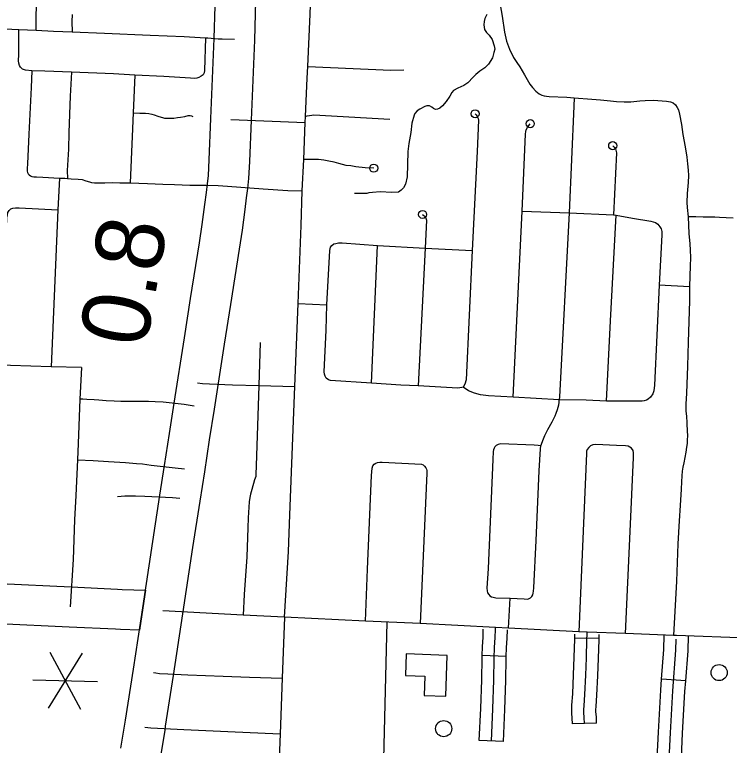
# Model space of a CAD drawing. Extents: x 653372 to 905732, y 627442 to 787275.
# Drawn here: x 688877 to 693311, y 773364 to 777895 of the extents above; entities that cross this region are included whole.
import ezdxf

# ---------------------------------------------------------------- set-up
doc = ezdxf.new("R2010")
doc.units = 0
for name, color, linetype in [('10', 7, 'Continuous'), ('32', 7, 'Continuous'), ('33', 7, 'Continuous'), ('34', 7, 'Continuous'), ('35', 7, 'Continuous'), ('48', 7, 'Continuous'), ('56', 7, 'Continuous'), ('58', 7, 'Continuous'), ('6', 7, 'Continuous')]:
    doc.layers.add(name, color=color, linetype=linetype)

msp = doc.modelspace()

# ---------------------------------------------------------------- linework, layer by layer
at = {"layer": '10'}
for points in [[(689536.7, 773346.1), (689560.5, 773495.3), (689564.1, 773520.3), (689614.1, 773835.2), (689671.8, 774217.4), (689733.5, 774627.8), (689778.5, 774916.3), (689807.4, 775098.7), (689837.2, 775296.7), (689866.9, 775486.7), (689929.8, 775890.1), (689968.3, 776135.9), (690023.1, 776479.5), (690040.6, 776594.7), (690056.9, 776718.6), (690066.3, 776792.3), (690074.1, 776846.8), (690079.2, 776898.2), (690083.7, 776995.5), (690093.7, 777250.6), (690115, 777746.6), (690126.4, 778153.9)], [(690376.3, 778145.3), (690364.8, 777737.8), (690343.5, 777240.3), (690333.5, 776984.8), (690328.7, 776880.1), (690322.4, 776816.7), (690314.1, 776758.7), (690304.8, 776686.4), (690288.1, 776559.7), (690270.2, 776441.1), (690215.2, 776096.9), (690176.9, 775851.5), (690113.9, 775448.2), (690084.3, 775258.8), (690054.4, 775060.6), (690025.5, 774877.5), (689980.6, 774590), (689919, 774180.1), (689861.2, 773796.9), (689811.3, 773483.1), (689807.8, 773458.1), (689783.7, 773307.2)], [(687265.9, 774433.2), (687410.6, 774429.4), (687546.1, 774423.7), (687592, 774420.9), (687915.2, 774404.3), (688264.9, 774389.4), (688488.7, 774378.5), (688787.8, 774366.5), (689227.2, 774347), (689516, 774333.1), (689544.5, 774331.3), (689688.3, 774327), (689650.8, 774078)], [(689650.8, 774078), (689533.1, 774081.6), (689502.4, 774083.5), (689215.7, 774097.2), (688777.2, 774116.7), (688477.6, 774128.8), (688253.6, 774139.6), (687903.4, 774154.6), (687578.1, 774171.3), (687533.4, 774174), (687402, 774179.6), (687259.3, 774183.3)]]:
    msp.add_lwpolyline(points, dxfattribs=at)
at = {"layer": '32'}
for p, q in [((692502.6, 774025.7), (692352.6, 774028.1)), ((691927.3, 773914.9), (691777.5, 773920.8)), ((693040.1, 773763), (692890.5, 773774.7)), ((692486.8, 773501), (692336.9, 773498)), ((691909.5, 773386.8), (691759.7, 773393.6))]:
    msp.add_line(p, q, dxfattribs=at)
for points in [[(691777.5, 773920.8), (691779.6, 773974.8), (691782.9, 774035.4), (691784.7, 774085)], [(691834.6, 773390.2), (691843.6, 773589.7), (691849.6, 773767.8), (691851.9, 773904.5), (691854.5, 773971.2), (691857.8, 774031.9), (691859.7, 774082.2)], [(691927.3, 773914.9), (691929.4, 773967.7), (691932.8, 774028.5), (691934.6, 774079.5)], [(692352.6, 774028.1), (692353, 774052.7)], [(692336.9, 773498), (692336.2, 773532.3), (692333.4, 773564.2), (692333.3, 773588.2), (692334.7, 773613.2), (692339.3, 773682.5), (692344.7, 773802.1), (692349.1, 773910.1), (692352.5, 774022.4), (692352.6, 774028.1)], [(692411.8, 773499.5), (692411.1, 773536.3), (692408.4, 773567.6), (692408.3, 773586.2), (692409.6, 773608.6), (692414.2, 773678.4), (692419.6, 773798.9), (692424.1, 773907.4), (692427.5, 774020.7), (692428, 774051.5)], [(692486.8, 773501), (692486, 773540.3), (692483.4, 773571), (692483.3, 773584.2), (692484.5, 773604), (692489, 773674.2), (692494.5, 773795.7), (692499, 773904.7), (692502.5, 774018.9), (692502.6, 774025.7)], [(692502.6, 774025.7), (692503, 774050.3)], [(692890.5, 773774.7), (692904.9, 773958), (692907.6, 774047.5)], [(692930.4, 772714), (692924.4, 772800), (692927.7, 772910.2), (692932.1, 773057.1), (692936.2, 773235.9), (692946.1, 773442.3), (692960, 773701.7), (692979.9, 773953.9), (692981.9, 774021.6)], [(693040.1, 773763), (693054.8, 773949.8), (693057.6, 774042.7)], [(691759.7, 773393.6), (691768.7, 773592.6), (691774.6, 773769.7), (691776.9, 773906.6), (691777.5, 773920.8)], [(691909.5, 773386.8), (691918.6, 773586.7), (691924.6, 773765.9), (691926.9, 773902.4), (691927.3, 773914.9)], [(692861.6, 773245.2), (692871.2, 773446.1), (692885.2, 773706.6), (692890.5, 773774.7)], [(693011.4, 773238.1), (693021, 773438.5), (693034.9, 773696.7), (693040.1, 773763)]]:
    msp.add_lwpolyline(points, dxfattribs=at)
at = {"layer": '33'}
for points in [[(690550.6, 774158.3), (690575.6, 774566.7), (690583.4, 774794.3), (690615.6, 775588.4), (690635.5, 776104.2), (690654, 776588.6), (690661.4, 776802.5), (690670.9, 776996.8), (690678.7, 777225.6), (690681.8, 777264.6), (690690.8, 777501.7), (690696.6, 777572.9), (690711, 777897.6), (690715.4, 778011.1), (690718.5, 778085.4), (690718.1, 778132), (690718.9, 778221.3), (690716.2, 778348), (690715.4, 778462.1)], [(689010.4, 777798.4), (689010.7, 777894.8), (689016.4, 778027.3)], [(689233.4, 777895.5), (689232.7, 777853.6), (689233.8, 777788.2)], [(688052.5, 777836.9), (688146.7, 777834.1), (688304, 777826.6), (688436.3, 777820.5), (688587.6, 777816.7), (688643.2, 777815), (688903.1, 777803.7), (689010.4, 777798.4), (689117.4, 777792.4), (689233.8, 777788.2), (689434, 777779.4), (689717.1, 777767.5), (689929.1, 777759), (690061.3, 777752.3), (690076.5, 777751.8), (690138.8, 777745.8), (690163.5, 777744.3), (690239.9, 777742.2)], [(690061.3, 777752.3), (690055.1, 777548.3), (690052, 777535.2), (690046.7, 777522.9), (690033.3, 777513.6), (690019.8, 777505), (690007.2, 777500.5), (689994.7, 777499.5), (689967, 777501.7), (689801.5, 777511.5), (689622.7, 777520.1), (689489.6, 777528.5), (689230.7, 777537.6), (689063.5, 777545.5), (688983.4, 777546.5), (688944, 777551.1), (688925.4, 777558), (688913.3, 777568.7), (688906.7, 777580), (688902.2, 777594.7), (688901.3, 777608.6), (688902.5, 777648.2), (688903.1, 777803.7)], [(688983.4, 777546.5), (688979.1, 777444.5), (688965.2, 777155), (688957.3, 776970.6), (688955.5, 776942.1), (688955.4, 776925), (688957.5, 776915.4), (688961.1, 776908.8), (688967.6, 776901.5), (688974.5, 776895.1), (688983, 776892.5), (688996.7, 776889.7), (689013.4, 776889.2), (689051.4, 776887.6), (689154.4, 776881.6), (689187.7, 776881.1), (689203.9, 776880.1), (689227.6, 776878), (689271, 776874.8), (689295.7, 776872.1), (689319.6, 776864.8), (689340.8, 776858.4), (689354, 776854.7), (689372.5, 776852.7), (689401.2, 776852.3), (689436.4, 776852.2), (689483.9, 776854.1), (689529.7, 776853.2), (689594.1, 776851.8), (689701.5, 776847.6), (689796.1, 776844.7), (689869.3, 776841.6), (689963.2, 776838.8), (690064.4, 776837.2), (690140.5, 776835.4), (690198.3, 776831.8)], [(690696.6, 777572.9), (691211.4, 777550.1), (691292.2, 777553.3)], [(689230.7, 777537.6), (689221.7, 777390.3), (689213.8, 777165.1), (689211.2, 777060.8), (689203.2, 776929.7), (689203.9, 776880.1)], [(689622.7, 777520.1), (689611.4, 777285.6), (689605.4, 777140.5), (689594.1, 776851.8)], [(692346.7, 777328.2), (692316.2, 776666.5), (692257.5, 775524.6), (692255, 775507.3)], [(690681.8, 777264.6), (690691.9, 777266.9), (690707.2, 777269.7), (690721.7, 777272.4), (690733, 777273.7), (691205.5, 777247.5)], [(691733.9, 777280.5), (691740, 777274.1), (691747.4, 777263), (691753.3, 777251.1), (691755.3, 777240.1), (691745.6, 777046.2), (691716.2, 776432.4), (691677.4, 775631.1), (691670.3, 775604), (691659.3, 775584.6), (691651, 775582.7), (691627.5, 775579.6), (691379.9, 775594), (691273.8, 775597.9), (691089.9, 775609.7), (690837.2, 775626.6), (690823.9, 775631), (690810.2, 775641.5), (690802.8, 775654.2), (690799.3, 775665.2), (690796.7, 775680.1), (690810.6, 775937.9), (690814.6, 776094.7), (690833.3, 776433.5), (690837, 776453.6), (690845.1, 776463.5), (690857.1, 776473.3), (690868.9, 776476.9), (690885.4, 776480.3), (690909.6, 776479.5), (691129, 776464.4), (691423.2, 776446.8), (691716.2, 776432.4)], [(690218.6, 777245.4), (690678.7, 777225.6)], [(691969.4, 775523.8), (691993.2, 775995.5), (692026.1, 776676.8), (692046.7, 777155.1), (692048.8, 777171.4), (692050.7, 777181.5), (692058.1, 777194.6), (692067.8, 777208.3), (692076, 777219)], [(692587.3, 777082.6), (692595.6, 777073.8), (692604.6, 777062.6), (692607.5, 777053.9), (692610.9, 777038.2), (692591.6, 776653)], [(691104.9, 776943.2), (691052, 776945.6), (690993.7, 776952.2), (690961.7, 776957.2), (690934.6, 776960.4), (690887.6, 776973), (690859, 776980.3), (690826.3, 776986.9), (690795.1, 776991.9), (690761.6, 776996.9), (690722.3, 776996.5), (690670.9, 776996.8)], [(689154.4, 776881.6), (689145.4, 776685.4), (689102.5, 775712.1)], [(690198.3, 776831.8), (690279.9, 776825.2), (690418.7, 776815.1), (690571.1, 776805.4), (690661.4, 776802.5)], [(689291, 775706.1), (689102.5, 775712.1), (688851.9, 775718.9), (688829.3, 775722.3), (688815.3, 775728.1), (688802.8, 775740.7), (688793.1, 775755.8), (688790.9, 775770.8), (688792.6, 775807.9), (688800.7, 776007.1), (688819.3, 776402.1), (688829, 776634.7), (688831.8, 776651.9), (688835.6, 776668.9), (688842.7, 776680.9), (688853.6, 776690.1), (688866.6, 776694.4), (688881.9, 776697), (688904.5, 776697.4), (689145.4, 776685.4)], [(691407.7, 776656.3), (691415.3, 776649.8), (691423.6, 776641), (691427.3, 776633.9), (691431.6, 776621.3), (691423.2, 776446.8)], [(692026.1, 776676.8), (692316.2, 776666.5), (692591.6, 776653), (692607.9, 776651), (692709.3, 776633.6), (692824.2, 776615.4), (692852, 776606.7), (692868.1, 776595.3), (692879.3, 776579.4), (692887.5, 776566.6), (692891.7, 776550.9), (692891.8, 776529.9), (692875.7, 776217.1), (692845.9, 775596.5), (692842.5, 775561.5), (692835.7, 775543.8), (692821.8, 775523.9), (692807.4, 775510.3), (692796.3, 775505.2), (692782.2, 775500.9), (692769.6, 775499), (692656.5, 775497.5), (692549.7, 775498.4), (692422, 775503.9), (692255, 775507.3), (691969.4, 775523.8), (691817.5, 775531.4), (691767.1, 775538.4), (691729.9, 775548.1), (691693, 775563.3), (691659.3, 775584.6)], [(692549.7, 775498.4), (692574.2, 775997.4), (692607.9, 776651)], [(691089.9, 775609.7), (691129, 776464.4)], [(691423.2, 776446.8), (691379.9, 775594)], [(693063.4, 776207.6), (692875.7, 776217.1)], [(690635.5, 776104.2), (690814.6, 776094.7)], [(690401, 775862), (690391.3, 775596.3), (690375.2, 775096.2), (690373.7, 775045.9), (690372.8, 775032), (690364.4, 775010.5), (690348.7, 774951), (690339.5, 774920.5), (690335.4, 774899.9), (690332.9, 774874.8), (690330.2, 774841.4), (690326.4, 774774.6), (690323.2, 774711.7), (690317.9, 774533.6), (690300.9, 774299.3), (690294.9, 774171.4)], [(689291, 775706.1), (689281.3, 775511.3), (689271.1, 775235.4), (689266.3, 775134.1), (689256.2, 774914.1), (689249, 774762.2), (689239.2, 774516.8), (689221.4, 774222.1)], [(690012.1, 775611.2), (690042.3, 775606.8), (690084.9, 775605.5), (690228.9, 775599.5), (690391.3, 775596.3), (690615.6, 775588.4)], [(691951.9, 774276), (692037.9, 774271.7), (692058, 774271.1), (692065.9, 774272.6), (692077.8, 774278.9), (692086.4, 774287.6), (692091.7, 774297), (692094.8, 774306.9), (692096.9, 774319.2), (692098.7, 774340.9), (692111.9, 774633.7), (692131.1, 775066.6), (692139.6, 775202.4), (692141.9, 775221.2), (692145.5, 775232.4), (692153.5, 775255.1), (692166.7, 775284.4), (692184.6, 775321.9), (692211.7, 775369.2), (692230.7, 775406.6), (692236.8, 775423.4), (692244.8, 775446.1), (692252.9, 775475.5), (692254.5, 775490), (692255, 775507.3)], [(693046.8, 775357.7), (693049.7, 775313.8), (693050.5, 775284.2), (693050.3, 775258.4), (693048.5, 775236.7), (693045.5, 775212.2), (693040.7, 775181.6), (693034.2, 775149.3), (693028.1, 775115.4), (693022.8, 775088.7), (693019.3, 775064), (693016.8, 775036.2), (693014, 774997.7), (693011.5, 774951.9), (693005.1, 774850.8), (693000, 774755.4), (692991.8, 774614.5), (692982.1, 774382.2), (692965.1, 774045.2)], [(692141.9, 775221.2), (692124, 775222.8), (692100.4, 775224.5), (691891.6, 775232.8), (691876.6, 775230.2), (691864.6, 775223.3), (691856.6, 775215.4), (691851.2, 775206.3), (691848.3, 775196.1), (691845.9, 775185.4), (691844.5, 775136.1), (691813.9, 774459.5), (691806.1, 774338), (691807.7, 774321.5), (691811.4, 774309.5), (691817.8, 774298.6), (691825.8, 774290.6), (691835.9, 774285.2), (691845.5, 774281.8), (691862.4, 774279.2), (691951.9, 774276)], [(692667.6, 774056.9), (692696.1, 774689), (692717.1, 775148.1), (692716.9, 775177.2), (692713.5, 775192.9), (692703.8, 775206.6), (692694.5, 775213.6), (692682.4, 775219), (692666.8, 775220.6), (692611.5, 775223.4), (692482.8, 775228.9), (692463.2, 775227.8), (692450.1, 775221.5), (692438.6, 775211.2), (692429.3, 775199.2), (692425.6, 775187.6), (692425.2, 775173.1), (692378.2, 774067.5)], [(689266.3, 775134.1), (689363.1, 775129.9), (689458.6, 775124.6), (689564, 775117.7), (689632.8, 775112.5), (689669.3, 775109.5), (689724.4, 775101.7), (689779.2, 775095.1), (689872.7, 775084.8), (689930.9, 775079.6)], [(691053.9, 774134.6), (691066.3, 774455.7), (691090, 775037), (691094.5, 775082.8), (691099.6, 775097.5), (691107.7, 775107.4), (691117.3, 775113.4), (691127.5, 775117.7), (691143.2, 775119.6), (691158, 775119.9), (691400.9, 775108), (691410.9, 775103), (691420, 775094.9), (691428.3, 775084.5), (691432.7, 775076.6), (691434.8, 775067.9), (691435.1, 775050.8), (691393, 774119.4)], [(689514.1, 774906.3), (689561.3, 774910.9), (689626.2, 774911.4), (689684.2, 774909.6), (689855.8, 774900.2), (689902, 774896.9)], [(691940.2, 774090.1), (691951.9, 774276)], [(694614.2, 773970.5), (694233.4, 773989.4), (693983.5, 774002.5), (693423.7, 774028.6), (692982.8, 774045.6), (692965.1, 774045.2), (692667.6, 774056.9), (692428.2, 774064.8), (692378.2, 774067.5), (691940.2, 774090.1), (691859.4, 774094.8), (691393, 774119.4), (691053.9, 774134.6), (690550.6, 774158.3), (690294.9, 774171.4), (689795.4, 774198.8)], [(690550.6, 774158.3), (690536.4, 773780.4), (690524.3, 773436.2), (690508.8, 773073.9), (690491.1, 772706), (690480.8, 772447), (690466, 772107.6), (690448.5, 771700), (690443.2, 771543.8), (690439.1, 771517.9), (690430.4, 771489.9), (690414, 771469.4), (690387.9, 771452.4), (690369.3, 771447.7), (690347.6, 771445.1), (690316.8, 771447.3), (690244, 771451.5), (690096.2, 771459.4), (689548.1, 771483.6), (689384.5, 771488.3)], [(691859.7, 774082.2), (691859.4, 774094.8)], [(692428, 774051.5), (692428.2, 774064.8)], [(689737.6, 773816), (689753.8, 773812.5), (689775.1, 773809.3), (689827.8, 773807.7), (689951.5, 773802.1), (690170.9, 773793.7), (690334.9, 773786), (690536.4, 773780.4)], [(689684.1, 773476.7), (689722.5, 773472.2), (689927.1, 773462.7), (690200, 773450), (690524.3, 773436.2)]]:
    msp.add_lwpolyline(points, dxfattribs=at)
for centre in [(691733.9, 777280.5), (692076, 777219), (692587.3, 777082.6), (691104.9, 776943.2), (691407.7, 776656.3)]:
    msp.add_circle(centre, 25, dxfattribs=at)
at = {"layer": '34'}
for points in [[(691861.9, 778062.2), (691872.4, 778026), (691889.2, 777956.6), (691901.3, 777886.1), (691916.5, 777786.2), (691929.2, 777731.2), (691946.5, 777681.9), (691971.6, 777629.2), (691992.8, 777598.1), (692010.8, 777571.3), (692040.5, 777521.6), (692073.2, 777464.7), (692089.5, 777442.8), (692109.6, 777421.4), (692130.5, 777404.5), (692148.5, 777396.2), (692162, 777391.2), (692175.6, 777389.5), (692193.1, 777387.7), (692301.8, 777383.1), (692347.6, 777379.8)], [(692347.6, 777379.8), (692346.7, 777328.2)], [(692347.6, 777379.8), (692458.6, 777372), (692512.1, 777366.5), (692573.4, 777360.2), (692611, 777356.8), (692659, 777354.8), (692699.3, 777355.3), (692756.5, 777360.9), (692789.5, 777363.2), (692841, 777363.9), (692920.8, 777359.3), (692946.9, 777354.6), (692962.9, 777347.9), (692977.1, 777336.3), (692987.8, 777320.4), (692995.7, 777304.5), (693002.2, 777279.1), (693014.8, 777213.9), (693022.5, 777152.7), (693036.7, 777075.4), (693046.5, 777011.9), (693051.4, 776969.8), (693055.2, 776931.1), (693057.6, 776898.6), (693055.2, 776855.1), (693049.8, 776786.3), (693047.6, 776731), (693049.7, 776699), (693054.7, 776640.8)], [(689611.4, 777285.6), (689654.6, 777284.7), (689689.4, 777283.4), (689709.5, 777281.8), (689727.1, 777278.5), (689742.5, 777274.3), (689766.3, 777265.8), (689786, 777259.6), (689794.8, 777256.9), (689807, 777254.2), (689820.2, 777253.2), (689836.5, 777252.5), (689845.4, 777252.5), (689864.4, 777252.4), (689886.5, 777256.6), (689906.9, 777259.2), (689933.3, 777263.8), (689953.6, 777268.8), (689965.1, 777269.3), (689974.4, 777268.4), (689982.3, 777263.9)], [(693054.7, 776640.8), (693060.2, 776537.1), (693065, 776473.8), (693068.3, 776434.4), (693069.2, 776390.2), (693067.6, 776336), (693066.8, 776274.5), (693063.4, 776207.6), (693063.9, 776120.3), (693055.1, 775864.9), (693050.6, 775715.1), (693044.5, 775548), (693041.8, 775478.8), (693041.2, 775439.1), (693044.6, 775403.2), (693046.2, 775365.7), (693046.8, 775357.7)], [(693333.9, 776633), (693291, 776636), (693249.7, 776638.3), (693221.7, 776639.2), (693148.2, 776640.3), (693103, 776641.1), (693082.9, 776641.1), (693054.7, 776640.8)], [(689990.4, 775467.4), (689928.5, 775476.8), (689835.5, 775488.2), (689799, 775491.8), (689748.4, 775494.8), (689706.8, 775495.5), (689671.7, 775497.1), (689596.7, 775496.3), (689536, 775497.1), (689494.4, 775498.9), (689444.3, 775500.9), (689399.8, 775504.2), (689369.7, 775506.2), (689325.3, 775508.5), (689300.8, 775511.2), (689281.3, 775511.3)]]:
    msp.add_lwpolyline(points, dxfattribs=at)
at = {"layer": '35'}
msp.add_lwpolyline([(691807, 777896.9), (691793.9, 777872), (691789.4, 777851.9), (691788.8, 777833.1), (691789, 777818.2), (691792.5, 777803.1), (691804.3, 777784.6), (691820.7, 777768.5), (691839.3, 777740.6), (691851.2, 777702.5), (691855.7, 777680.3), (691850.6, 777660.3), (691841.8, 777627.4), (691817.3, 777589.2), (691793.1, 777564.5), (691762.7, 777545.4), (691737.3, 777524.1), (691720.6, 777507), (691688.3, 777472.3), (691663.8, 777455.4), (691627, 777440.3), (691600.5, 777425), (691588.4, 777411.7), (691576.1, 777390.7), (691554.9, 777356.8), (691532, 777330.2), (691515.3, 777315.1), (691500.9, 777309.1), (691488.5, 777307.5), (691475.6, 777313.1), (691464.2, 777322.5), (691450.8, 777329.4), (691433.2, 777329.3), (691422.1, 777325.7), (691390.4, 777309.2), (691373.8, 777298), (691359.7, 777281.5), (691355.2, 777271.4), (691342, 777222.4), (691335.1, 777164.7), (691323.2, 777095.5), (691315.9, 777046.3), (691314.8, 776966.2), (691311.9, 776889.6), (691302.1, 776844.4), (691290.3, 776822), (691274.9, 776806.2), (691258.3, 776794.3), (691217.3, 776793), (691145.3, 776795.8), (691097.1, 776793.3), (691075, 776790.1), (691061.2, 776786.6), (691033.9, 776786.1), (691011.3, 776785.5), (690984.6, 776785.6)], dxfattribs=at)
at = {"layer": '48'}
for p, q in [((689295.6, 773935.3), (689085.3, 773595)), ((689095.6, 773941.3), (689285.2, 773589)), ((688990.5, 773771.1), (689390.3, 773759.1))]:
    msp.add_line(p, q, dxfattribs=at)
at = {"layer": '56'}
for centre in [(693247.6, 773815), (691538.8, 773467.4)]:
    msp.add_circle(centre, 50, dxfattribs=at)
at = {"layer": '58'}
msp.add_lwpolyline([(691560.7, 773921.8), (691306.8, 773931.1), (691301.9, 773797.2), (691422, 773792.8), (691417.6, 773672.9), (691551.3, 773667.9)], close=True, dxfattribs=at)
at = {"layer": '6'}
msp.add_lwpolyline([(691185.5, 774128.3), (691133.7, 772008.9), (691797.9, 771972.6), (691838.2, 772791.2), (692320.3, 772761), (692280.2, 772096.9), (693061.3, 772051.7), (693031.2, 771391.2), (692868.8, 771399.5), (692822.7, 770157.5)], dxfattribs=at)

# ---------------------------------------------------------------- texts
at = {"layer": '48'}
msp.add_text('0.8', height=422.4, rotation=80.0068, dxfattribs=at).set_placement((689690.6, 775820.2))

doc.saveas('drawing.dxf')
